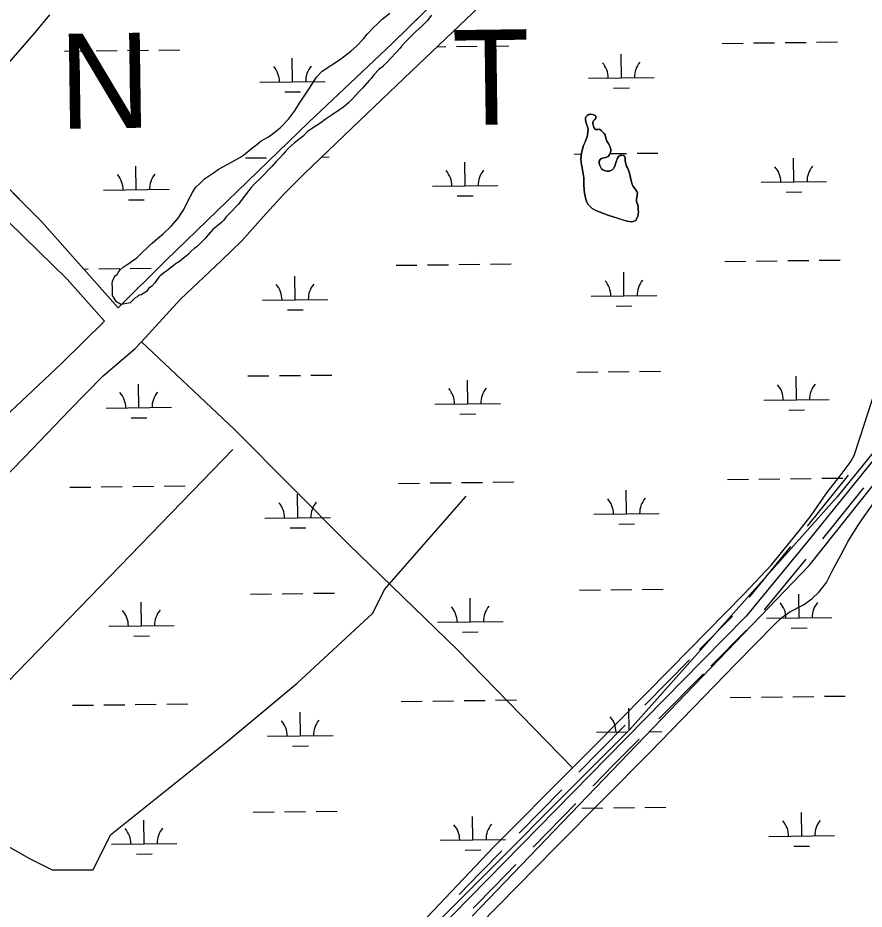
# Model space of a CAD drawing. Extents: x 3694830 to 3732949, y 415201 to 440970.
# Drawn here: x 3723273 to 3724564, y 421416 to 422776 of the extents above; entities that cross this region are included whole.
import ezdxf

# ---------------------------------------------------------------- set-up
doc = ezdxf.new("R2010")
doc.units = 0
for name, color, linetype in [('V-ROAD-CNTR', 7, 'Continuous'), ('V-SITE-VEGE', 7, 'Continuous'), ('V-TOPO-GNAM-IDEN', 7, 'Continuous'), ('V-TOPO-SHOR', 7, 'Continuous'), ('V-WETL-SWMP', 7, 'Continuous')]:
    doc.layers.add(name, color=color, linetype=linetype)

msp = doc.modelspace()

# ---------------------------------------------------------------- linework, layer by layer
at = {"layer": 'V-ROAD-CNTR'}
for points in [[(3724786.4, 422355), (3724602.6, 422131.6), (3724478.4, 421977.9), (3724384.4, 421863.4), (3724317.6, 421795.5)], [(3724540.2, 422078.3), (3724477.4, 422000.5)], [(3724563.5, 422059.4), (3724500.7, 421981.6)], [(3724452.2, 421969.6), (3724388.7, 421892.3)], [(3724475.3, 421950.5), (3724411.9, 421873.3)], [(3724363.2, 421863.3), (3724313.1, 421812.4)], [(3724384.6, 421842.2), (3724330.5, 421787.3)], [(3724317.6, 421795.5), (3724172.3, 421648), (3723806.9, 421275.5), (3723498.2, 420963.7)], [(3724297.7, 421796.8), (3724229.8, 421727.7)], [(3724319, 421775.6), (3724251.2, 421706.7)], [(3724199.5, 421697), (3724161.6, 421658.5)], [(3724220.9, 421675.9), (3724183, 421637.4)], [(3724161.6, 421658.5), (3724129, 421625.2)], [(3724183, 421637.4), (3724150.4, 421604.2)], [(3724102.9, 421598.6), (3724037.6, 421532.1)], [(3724124.3, 421577.6), (3724059, 421511.1)], [(3724011.5, 421505.5), (3723978.9, 421472.2)], [(3723978.9, 421472.2), (3723946.3, 421439)], [(3724032.9, 421484.5), (3724000.3, 421451.2)], [(3724000.3, 421451.2), (3723967.7, 421418)]]:
    msp.add_lwpolyline(points, dxfattribs=at)
at = {"layer": 'V-SITE-VEGE'}
for points in [[(3723469.1, 422358.5), (3723460.6, 422353.8), (3723458.1, 422353.2), (3723456.2, 422352), (3723454.4, 422350.1), (3723451.9, 422348.9), (3723450, 422347.7), (3723448.8, 422345.8), (3723443.8, 422341.5), (3723438.9, 422340.2), (3723429.6, 422339), (3723427.7, 422340.2), (3723423.4, 422342.7), (3723420.9, 422345.8), (3723419.7, 422348.3), (3723417.2, 422352.6), (3723417.2, 422366.2), (3723416.6, 422370), (3723417.2, 422374.3), (3723419.7, 422379.9), (3723421.6, 422383), (3723424, 422384.8), (3723425.9, 422387.9), (3723429, 422391.6), (3723433.3, 422396), (3723439.5, 422399.7), (3723442, 422401.5), (3723445.9, 422404.6), (3723454, 422410.1), (3723458.9, 422414.5), (3723472.5, 422428.1), (3723477.5, 422432.4), (3723485.5, 422439.8), (3723494.2, 422446.6), (3723507.2, 422459), (3723517.1, 422470.8), (3723522.7, 422479.4), (3723525.8, 422483.8), (3723533.2, 422498.6), (3723539.4, 422509.8), (3723543.8, 422517.2), (3723550.6, 422523.4), (3723557.4, 422530.8), (3723571, 422539.5), (3723579.7, 422545.7), (3723593.3, 422553.1), (3723603.2, 422558.7), (3723612.5, 422563.6), (3723616.8, 422566.7), (3723628.6, 422576.6), (3723637.3, 422582.8), (3723644.1, 422588.4), (3723655.2, 422594.6), (3723660.8, 422598.9), (3723673.2, 422608.2), (3723685.6, 422621.8), (3723694.9, 422633.6), (3723703.5, 422647.8), (3723717.8, 422668.8), (3723728.3, 422685.5), (3723737, 422694.8), (3723764.9, 422713.4), (3723781, 422725.2), (3723789.6, 422733.2), (3723800.2, 422744.3), (3723805.7, 422751.1), (3723816.3, 422762.3), (3723821.2, 422766.6), (3723828.6, 422774), (3723840.4, 422783.3)], [(3723904.2, 422780.2), (3723897.4, 422771.5), (3723889.9, 422764.1), (3723879.4, 422754.8), (3723862.1, 422737.5), (3723858.3, 422733.2), (3723855.9, 422730.1), (3723835.4, 422707.8), (3723830.5, 422703.5), (3723829.2, 422701.6), (3723824.3, 422697.9), (3723816.2, 422689.2), (3723811.9, 422683.7), (3723809.4, 422681.2), (3723798.9, 422668.8), (3723793.3, 422663.2), (3723783.4, 422652.7), (3723777.2, 422646.5), (3723769.8, 422639.7), (3723763.6, 422636), (3723752.4, 422628), (3723741.9, 422621.2), (3723735.1, 422616.2), (3723720.9, 422606.9), (3723714.7, 422602.6), (3723707.9, 422595.8), (3723694.9, 422585.3), (3723685.6, 422577.2), (3723680.6, 422571.6), (3723676.9, 422567.9), (3723672.6, 422562.4), (3723667, 422556.8), (3723660.2, 422549.4), (3723641, 422529.6), (3723634.8, 422524), (3723628.6, 422517.2), (3723619.9, 422506), (3723615, 422499.8), (3723609.4, 422491.8), (3723596.4, 422478.2), (3723590.8, 422472.6), (3723586.5, 422467), (3723584, 422464.6), (3723570.4, 422453.4), (3723559.8, 422441.7), (3723558.6, 422439.8), (3723545.6, 422426.8), (3723541.9, 422424.3), (3723536.9, 422420), (3723532.6, 422415.1), (3723530.1, 422413.2), (3723517.7, 422403.3), (3723514.6, 422402.1), (3723509.1, 422397.1), (3723507.2, 422395.9), (3723499.8, 422390.3), (3723495.4, 422387.2), (3723489.2, 422382.3), (3723488, 422380.4), (3723483.7, 422374.8), (3723481.8, 422371.7), (3723476.9, 422366.8), (3723471.9, 422363.1), (3723470.7, 422360.6), (3723469.1, 422358.5)]]:
    msp.add_lwpolyline(points, dxfattribs=at)
at = {"layer": 'V-TOPO-SHOR'}
msp.add_line((3723053.4, 421553.2), (3723600.9, 422117.5), dxfattribs=at)
for points in [[(3723843.6, 422736.3), (3723921.9, 422813.8)], [(3723873.4, 422694.7), (3723977.1, 422793.5)], [(3723321.1, 422780.8), (3723299, 422754.3), (3723238, 422684.7)], [(3723425.5, 422333.8), (3723499.1, 422406.4), (3723716.6, 422617.2), (3723843.6, 422736.3)], [(3723191.8, 422013.3), (3723283.2, 422106.5), (3723351.6, 422177.8), (3723402.8, 422229.8), (3723451, 422271.1), (3723461.1, 422282.1), (3723520.8, 422346.9), (3723583.4, 422405.8), (3723614.3, 422436.2), (3723647, 422472.6), (3723678.2, 422506.7), (3723709.6, 422538.4), (3723782.6, 422607.9), (3723873.4, 422694.7)], [(3723233.6, 422648), (3723224.2, 422631.8), (3723206.7, 422605.2), (3723201.9, 422591.2), (3723201.1, 422581.5), (3723205.4, 422571.5), (3723220.7, 422553.5), (3723308.7, 422465.5), (3723425.5, 422333.8)], [(3724218.8, 422473.6), (3724215.9, 422467.1), (3724213.3, 422465.8), (3724209.4, 422464.9), (3724202.4, 422465.8), (3724194.8, 422468.2), (3724187.3, 422470.7), (3724179.5, 422473.2), (3724173, 422475.3), (3724168.1, 422477.3), (3724161.5, 422479.7), (3724154.7, 422482.3), (3724149.2, 422485.4), (3724143.2, 422491.2), (3724141.2, 422495), (3724139.7, 422499.7), (3724137.5, 422508.9), (3724136.3, 422520.3), (3724136.5, 422525.9), (3724136.5, 422532), (3724133.8, 422547.6), (3724133, 422551.7), (3724132.5, 422556.7), (3724132.1, 422560.7), (3724132.4, 422565.3), (3724133, 422570.3), (3724136, 422581.3), (3724137.8, 422585.5), (3724139.7, 422589.6), (3724141.4, 422594.9), (3724142.8, 422601.3), (3724143, 422606.6), (3724141.6, 422611.2), (3724140.1, 422615.6), (3724139.1, 422620.5), (3724139, 422623.9), (3724139.9, 422625.6), (3724140.6, 422626.4), (3724141.5, 422627.4), (3724144.3, 422628.7), (3724146.8, 422629.1), (3724150.1, 422628.7), (3724151.6, 422628.4), (3724153.6, 422627.4), (3724154.8, 422626.2), (3724154.9, 422623.3), (3724152.6, 422620.6), (3724150.6, 422618.4), (3724150, 422615.3), (3724150.6, 422612.9), (3724152, 422608.7), (3724154.5, 422606.1), (3724155.8, 422605.7), (3724157.8, 422605.9), (3724160.2, 422606.2), (3724160.8, 422606.1), (3724163.1, 422604.3), (3724165.6, 422601.8), (3724167.6, 422599.6), (3724169, 422597.5), (3724169.8, 422594.5), (3724170.5, 422591.1), (3724171.7, 422587.8), (3724173.1, 422585.9), (3724174.9, 422583.4), (3724175.9, 422581.2), (3724177.1, 422577.6), (3724177.5, 422575.4), (3724177.5, 422572.7), (3724176.8, 422569.9), (3724175.5, 422567.6), (3724173.8, 422564.8), (3724170.1, 422563.1), (3724166.9, 422562.5), (3724163.6, 422561.6), (3724161.6, 422560), (3724160, 422557.5), (3724160, 422554.5), (3724160.7, 422551.1), (3724163.7, 422545.9), (3724166.3, 422544), (3724168.9, 422542.9), (3724172.2, 422542.1), (3724175.8, 422542.3), (3724179.5, 422544.1), (3724181.7, 422546.2), (3724183.9, 422550.1), (3724184.9, 422553.7), (3724186.4, 422558), (3724188.1, 422562), (3724189.5, 422564.5), (3724191.8, 422566.2), (3724194.3, 422566.9), (3724197, 422566.4), (3724199.2, 422564.5), (3724199.7, 422560.9), (3724199.7, 422557.5), (3724201.7, 422550), (3724203.4, 422547.2), (3724204.9, 422543.7), (3724206.2, 422539)], [(3723170.6, 422547.3), (3723190.8, 422530.4), (3723347.7, 422377.5), (3723405, 422313.6)], [(3724206.2, 422539), (3724207.5, 422532.8), (3724208.7, 422527.5), (3724210.2, 422522.3), (3724211.6, 422518.9), (3724213.7, 422516.1), (3724216, 422513.7), (3724217.5, 422511.2), (3724218.2, 422508.5), (3724218.1, 422505.1), (3724216.9, 422500.3), (3724216.9, 422496.2), (3724217.5, 422494.2), (3724218.2, 422492.3), (3724219.2, 422488.8), (3724219.6, 422483.7), (3724219.7, 422479.8), (3724219.4, 422476.9), (3724218.8, 422473.6)], [(3723198.6, 422117.2), (3723339.2, 422248.7), (3723405, 422313.6)], [(3723461.1, 422282.1), (3723603.4, 422148.3), (3723777.2, 421973.2), (3723943.4, 421812.5), (3724119.4, 421632.2)], [(3723870.1, 421375.4), (3723998.4, 421511), (3724119.4, 421632.2), (3724153, 421665.8), (3724268.1, 421782.5), (3724380.9, 421897.1), (3724422.7, 421941.9), (3724447.4, 421971.7), (3724465.4, 421993.7), (3724483.4, 422016.8), (3724507.5, 422051.4), (3724527.7, 422077.7), (3724543, 422097.8), (3724548.9, 422108.3), (3724558.5, 422136.7), (3724593.4, 422244.6)], [(3723129.1, 421601.2), (3723227, 421529.9), (3723289.3, 421494.3), (3723325, 421476.5), (3723387.3, 421476.5), (3723414, 421529.9), (3723592, 421672.4), (3723698.9, 421761.4), (3723814.6, 421868.2), (3723832.4, 421903.9), (3723957, 422046.3)], [(3723976.2, 421391.7), (3724093.6, 421511), (3724237.4, 421655.3), (3724368.7, 421790.9), (3724427.4, 421850.6), (3724438.6, 421861.6), (3724450.9, 421870.1), (3724471.7, 421880.8), (3724484.3, 421889.6), (3724495.7, 421900.3), (3724506.7, 421914.9), (3724516.8, 421933.9), (3724528.6, 421956.6), (3724539.8, 421977.9), (3724557.1, 422005.1), (3724580.3, 422037.7)]]:
    msp.add_lwpolyline(points, dxfattribs=at)
at = {"layer": 'V-WETL-SWMP'}
for p, q in [((3723921.9, 422813.8), (3723843.6, 422736.3)), ((3723873.5, 422694.7), (3723977.1, 422793.5)), ((3723843.6, 422736.3), (3723716.6, 422617.2)), ((3724347.7, 422737.3), (3724379.7, 422737.7)), ((3724395.7, 422737.9), (3724427.7, 422738.3)), ((3724443.7, 422738.4), (3724475.7, 422738.8)), ((3724491.7, 422739), (3724523.7, 422739.4)), ((3723344, 422725.3), (3723376, 422725.7)), ((3723392, 422725.9), (3723424, 422726.3)), ((3723440, 422726.5), (3723472, 422726.9)), ((3723488, 422727), (3723520, 422727.4)), ((3723912.6, 422732.1), (3723925.9, 422732.3)), ((3723941.9, 422732.5), (3723973.9, 422732.8)), ((3723989.9, 422733), (3724021.9, 422733.4)), ((3723691.9, 422678.7), (3723691.5, 422714.7)), ((3724193.8, 422684.7), (3724193.3, 422720.7)), ((3723782.6, 422607.9), (3723873.5, 422694.7)), ((3724143.8, 422684.1), (3724243.8, 422685.3)), ((3723641.9, 422678.1), (3723741.9, 422679.3)), ((3724182, 422669.1), (3724206, 422669.4)), ((3723680.1, 422663.2), (3723704.1, 422663.4)), ((3724141.5, 422627.4), (3724139.9, 422625.6)), ((3724144.3, 422628.7), (3724141.5, 422627.4)), ((3724146.8, 422629.1), (3724144.3, 422628.7)), ((3724151.6, 422628.4), (3724146.8, 422629.1)), ((3724153.6, 422627.4), (3724151.6, 422628.4)), ((3724154.8, 422626.2), (3724153.6, 422627.4)), ((3723716.6, 422617.2), (3723499.1, 422406.4)), ((3724139.9, 422625.6), (3724139, 422623.9)), ((3724139, 422623.9), (3724139.1, 422620.5)), ((3724139.1, 422620.5), (3724140.1, 422615.6)), ((3724140.1, 422615.6), (3724141.7, 422611.2)), ((3724150, 422615.3), (3724150.6, 422618.4)), ((3724152, 422608.7), (3724150, 422615.3)), ((3724150.6, 422618.4), (3724154.9, 422623.3)), ((3724154.9, 422623.3), (3724154.8, 422626.2)), ((3723709.6, 422538.4), (3723782.6, 422607.9)), ((3724142.8, 422601.3), (3724141.4, 422594.9)), ((3724141.7, 422611.2), (3724143, 422606.6)), ((3724143, 422606.6), (3724142.8, 422601.3)), ((3724154.5, 422606.1), (3724152, 422608.7)), ((3724155.8, 422605.7), (3724154.5, 422606.1)), ((3724160.2, 422606.2), (3724155.8, 422605.7)), ((3724160.8, 422606.1), (3724160.2, 422606.2)), ((3724163.1, 422604.3), (3724160.8, 422606.1)), ((3724165.6, 422601.8), (3724163.1, 422604.3)), ((3724167.6, 422599.6), (3724165.6, 422601.8)), ((3724139.7, 422589.6), (3724136, 422581.3)), ((3724141.4, 422594.9), (3724139.7, 422589.6)), ((3724169, 422597.5), (3724167.6, 422599.6)), ((3724169.8, 422594.5), (3724169, 422597.5)), ((3724170.5, 422591.1), (3724169.8, 422594.5)), ((3724171.7, 422587.8), (3724170.5, 422591.1)), ((3724173.1, 422585.9), (3724171.7, 422587.8)), ((3724136, 422581.3), (3724133, 422570.3)), ((3724174.9, 422583.4), (3724173.1, 422585.9)), ((3724175.9, 422581.2), (3724174.9, 422583.4)), ((3724177.1, 422577.6), (3724175.9, 422581.2)), ((3724176.8, 422569.9), (3724177.5, 422572.7)), ((3724177.5, 422575.4), (3724177.1, 422577.6)), ((3724177.5, 422572.7), (3724177.5, 422575.4)), ((3723619.9, 422562.4), (3723651.9, 422562.8)), ((3723736.3, 422563.8), (3723747.9, 422564)), ((3724121.7, 422568.4), (3724132.8, 422568.5)), ((3724132.4, 422565.3), (3724132.1, 422560.7)), ((3724132.1, 422560.7), (3724133, 422551.7)), ((3724133, 422570.3), (3724132.4, 422565.3)), ((3724160, 422557.5), (3724161.6, 422560)), ((3724161.6, 422560), (3724163.6, 422561.6)), ((3724163.6, 422561.6), (3724166.9, 422562.5)), ((3724166.9, 422562.5), (3724170.1, 422563.1)), ((3724170.1, 422563.1), (3724173.8, 422564.8)), ((3724173.8, 422564.8), (3724175.5, 422567.6)), ((3724175.5, 422567.6), (3724176.8, 422569.9)), ((3724176.4, 422569.1), (3724201.7, 422569.4)), ((3724188.1, 422562), (3724186.4, 422558)), ((3724189.5, 422564.5), (3724188.1, 422562)), ((3724191.8, 422566.2), (3724189.5, 422564.5)), ((3724194.3, 422566.9), (3724191.8, 422566.2)), ((3724197, 422566.4), (3724194.3, 422566.9)), ((3724199.2, 422564.5), (3724197, 422566.4)), ((3724199.7, 422560.9), (3724199.2, 422564.5)), ((3724199.7, 422557.5), (3724199.7, 422560.9)), ((3724217.7, 422569.6), (3724249.7, 422569.9)), ((3724457.1, 422526), (3724456.7, 422562)), ((3723308.7, 422465.5), (3723220.7, 422553.5)), ((3723453.4, 422514), (3723452.9, 422550)), ((3723955.2, 422520), (3723954.8, 422556)), ((3724133, 422551.7), (3724133.8, 422547.6)), ((3724133.8, 422547.6), (3724136.5, 422532)), ((3724160, 422554.5), (3724160, 422557.5)), ((3724160.7, 422551.1), (3724160, 422554.5)), ((3724163.7, 422545.9), (3724160.7, 422551.1)), ((3724166.3, 422544), (3724163.7, 422545.9)), ((3724181.7, 422546.2), (3724179.5, 422544.1)), ((3724183.9, 422550.1), (3724181.7, 422546.2)), ((3724184.9, 422553.7), (3724183.9, 422550.1)), ((3724186.4, 422558), (3724184.9, 422553.7)), ((3724201.7, 422550), (3724199.7, 422557.5)), ((3724203.4, 422547.2), (3724201.7, 422550)), ((3724204.9, 422543.7), (3724203.4, 422547.2)), ((3723678.2, 422506.7), (3723709.6, 422538.4)), ((3724136.5, 422532), (3724136.5, 422525.9)), ((3724168.9, 422542.9), (3724166.3, 422544)), ((3724172.2, 422542.1), (3724168.9, 422542.9)), ((3724175.8, 422542.3), (3724172.2, 422542.1)), ((3724179.5, 422544.1), (3724175.8, 422542.3)), ((3724206.2, 422539), (3724204.9, 422543.7)), ((3724208.7, 422527.5), (3724206.2, 422539)), ((3723905.3, 422519.4), (3724005.2, 422520.6)), ((3724136.5, 422525.9), (3724136.3, 422520.3)), ((3724136.3, 422520.3), (3724137.5, 422508.9)), ((3724210.2, 422522.3), (3724208.7, 422527.5)), ((3724211.6, 422518.9), (3724210.2, 422522.3)), ((3724213.8, 422516.1), (3724211.6, 422518.9)), ((3724407.1, 422525.4), (3724507.1, 422526.6)), ((3723403.4, 422513.4), (3723503.4, 422514.6)), ((3723647, 422472.6), (3723678.2, 422506.7)), ((3723943.4, 422504.4), (3723967.4, 422504.7)), ((3724137.5, 422508.9), (3724139.7, 422499.7)), ((3724216, 422513.7), (3724213.8, 422516.1)), ((3724217.5, 422511.2), (3724216, 422513.7)), ((3724216.9, 422500.3), (3724218.1, 422505.1)), ((3724218.2, 422508.5), (3724217.5, 422511.2)), ((3724218.1, 422505.1), (3724218.2, 422508.5)), ((3724445.3, 422510.4), (3724469.3, 422510.7)), ((3723441.6, 422498.4), (3723465.6, 422498.7)), ((3724139.7, 422499.7), (3724141.2, 422495)), ((3724141.2, 422495), (3724143.2, 422491.2)), ((3724143.2, 422491.2), (3724149.2, 422485.4)), ((3724216.9, 422496.2), (3724216.9, 422500.3)), ((3724217.5, 422494.2), (3724216.9, 422496.2)), ((3724218.2, 422492.3), (3724217.5, 422494.2)), ((3724219.2, 422488.8), (3724218.2, 422492.3)), ((3724149.2, 422485.4), (3724154.7, 422482.3)), ((3724154.7, 422482.3), (3724161.5, 422479.7)), ((3724161.5, 422479.7), (3724168.1, 422477.3)), ((3724168.1, 422477.3), (3724173, 422475.3)), ((3724219.6, 422483.7), (3724219.2, 422488.8)), ((3724219.4, 422476.9), (3724219.7, 422479.8)), ((3724219.7, 422479.8), (3724219.6, 422483.7)), ((3723425.5, 422333.8), (3723308.7, 422465.5)), ((3723614.3, 422436.2), (3723647, 422472.6)), ((3724173, 422475.3), (3724202.4, 422465.8)), ((3724202.4, 422465.8), (3724209.4, 422464.9)), ((3724209.4, 422464.9), (3724213.3, 422465.8)), ((3724213.3, 422465.8), (3724215.9, 422467.1)), ((3724215.9, 422467.1), (3724218.8, 422473.6)), ((3724218.8, 422473.6), (3724219.4, 422476.9)), ((3723583.4, 422405.8), (3723614.3, 422436.2)), ((3723499.1, 422406.4), (3723425.5, 422333.8)), ((3723520.8, 422346.9), (3723583.4, 422405.8)), ((3723849.8, 422398.7), (3723881.8, 422399)), ((3723897.8, 422399.2), (3723929.8, 422399.6)), ((3723945.8, 422399.8), (3723977.8, 422400.2)), ((3723993.8, 422400.4), (3724025.8, 422400.8)), ((3724351.7, 422404.6), (3724383.7, 422405)), ((3724399.7, 422405.2), (3724431.7, 422405.6)), ((3724447.7, 422405.8), (3724479.7, 422406.2)), ((3724495.7, 422406.4), (3724527.7, 422406.7)), ((3723373.1, 422393), (3723380, 422393.1)), ((3723396, 422393.2), (3723428, 422393.6)), ((3723444, 422393.8), (3723476, 422394.2)), ((3724197.7, 422352.1), (3724197.3, 422388.1)), ((3723695.9, 422346.1), (3723695.4, 422382.1)), ((3723461.1, 422282.1), (3723520.8, 422346.9)), ((3723645.9, 422345.5), (3723745.9, 422346.7)), ((3724147.7, 422351.5), (3724247.7, 422352.7)), ((3723684.1, 422330.5), (3723708.1, 422330.8)), ((3724185.9, 422336.5), (3724209.9, 422336.8)), ((3723451, 422271.1), (3723461.1, 422282.1)), ((3723402.8, 422229.8), (3723451, 422271.1)), ((3724125.7, 422235.8), (3724157.7, 422236.1)), ((3724173.7, 422236.3), (3724205.7, 422236.7)), ((3724221.7, 422236.9), (3724253.7, 422237.3)), ((3723351.6, 422177.8), (3723402.8, 422229.8)), ((3723623.8, 422229.8), (3723655.8, 422230.2)), ((3723671.8, 422230.4), (3723703.8, 422230.7)), ((3723719.8, 422230.9), (3723751.8, 422231.3)), ((3723959.2, 422187.3), (3723958.8, 422223.3)), ((3724461.1, 422193.3), (3724460.7, 422229.3)), ((3723457.3, 422181.4), (3723456.9, 422217.4)), ((3724660.1, 422214), (3724523.2, 422045.6)), ((3724411.1, 422192.7), (3724511.1, 422193.9)), ((3723407.3, 422180.8), (3723507.3, 422182)), ((3723909.2, 422186.7), (3724009.2, 422187.9)), ((3723283.2, 422106.5), (3723351.6, 422177.8)), ((3723445.5, 422165.8), (3723469.5, 422166.1)), ((3723947.4, 422171.8), (3723971.4, 422172.1)), ((3724449.3, 422177.8), (3724473.3, 422178)), ((3723191.8, 422013.3), (3723283.2, 422106.5)), ((3724480.8, 421941.4), (3724609.2, 422102.5)), ((3724355.7, 422072), (3724387.7, 422072.4)), ((3724403.7, 422072.6), (3724435.7, 422072.9)), ((3724451.7, 422073.1), (3724483.7, 422073.5)), ((3724499.7, 422073.7), (3724531.7, 422074.1)), ((3723351.9, 422060), (3723383.9, 422060.4)), ((3723399.9, 422060.6), (3723431.9, 422061)), ((3723447.9, 422061.2), (3723479.9, 422061.5)), ((3723495.9, 422061.7), (3723527.9, 422062.1)), ((3723853.8, 422066), (3723885.8, 422066.4)), ((3723901.8, 422066.6), (3723933.8, 422067)), ((3723949.8, 422067.2), (3723981.8, 422067.5)), ((3723997.8, 422067.7), (3724029.8, 422068.1)), ((3723699.8, 422013.4), (3723699.4, 422049.4)), ((3724201.7, 422019.4), (3724201.3, 422055.4)), ((3724523.2, 422045.6), (3724206.9, 421690.6)), ((3724151.7, 422018.8), (3724251.7, 422020)), ((3723649.8, 422012.8), (3723749.8, 422014)), ((3724189.9, 422003.8), (3724213.9, 422004.1)), ((3723688, 421997.9), (3723712, 421998.1)), ((3723965.8, 421405.9), (3724480.8, 421941.4)), ((3723627.8, 421897.1), (3723659.8, 421897.5)), ((3723675.8, 421897.7), (3723707.8, 421898.1)), ((3723723.8, 421898.3), (3723755.8, 421898.7)), ((3724129.7, 421903.1), (3724161.7, 421903.5)), ((3724177.7, 421903.7), (3724209.7, 421904.1)), ((3724225.7, 421904.3), (3724257.7, 421904.6)), ((3724465.1, 421860.7), (3724464.6, 421896.7)), ((3723461.3, 421848.7), (3723460.9, 421884.7)), ((3723963.2, 421854.7), (3723962.8, 421890.7)), ((3723913.2, 421854.1), (3724013.2, 421855.3)), ((3724415.1, 421860.1), (3724515.1, 421861.3)), ((3723411.3, 421848.1), (3723511.3, 421849.3)), ((3723951.4, 421839.1), (3723975.4, 421839.4)), ((3724453.2, 421845.1), (3724477.2, 421845.4)), ((3723449.5, 421833.1), (3723473.5, 421833.4)), ((3723499.9, 421729.1), (3723531.9, 421729.5)), ((3723857.8, 421733.4), (3723889.8, 421733.7)), ((3723905.8, 421733.9), (3723937.8, 421734.3)), ((3723953.8, 421734.5), (3723985.8, 421734.9)), ((3724001.8, 421735.1), (3724033.8, 421735.5)), ((3724359.7, 421739.3), (3724391.6, 421739.7)), ((3724407.6, 421739.9), (3724439.6, 421740.3)), ((3724455.6, 421740.5), (3724487.6, 421740.9)), ((3724503.6, 421741.1), (3724535.6, 421741.4)), ((3723355.9, 421727.4), (3723387.9, 421727.8)), ((3723403.9, 421727.9), (3723435.9, 421728.3)), ((3723451.9, 421728.5), (3723483.9, 421728.9)), ((3723703.8, 421680.8), (3723703.4, 421716.8)), ((3724205.6, 421689.3), (3724205.2, 421722.8)), ((3724206.9, 421690.6), (3723821.6, 421305.4)), ((3723653.8, 421680.2), (3723753.8, 421681.4)), ((3724155.7, 421686.2), (3724203, 421686.7)), ((3724236.2, 421687.1), (3724255.7, 421687.4)), ((3723692, 421665.2), (3723716, 421665.5)), ((3724133.6, 421570.5), (3724165.6, 421570.8)), ((3724181.6, 421571), (3724213.6, 421571.4)), ((3724229.6, 421571.6), (3724261.6, 421572)), ((3723631.8, 421564.5), (3723663.8, 421564.9)), ((3723679.8, 421565), (3723711.8, 421565.4)), ((3723727.8, 421565.6), (3723759.8, 421566)), ((3723967.2, 421522), (3723966.7, 421558)), ((3724469, 421528), (3724468.6, 421564)), ((3723465.3, 421516.1), (3723464.8, 421552.1)), ((3724419, 421527.4), (3724519, 421528.6)), ((3723415.3, 421515.5), (3723515.3, 421516.7)), ((3723917.2, 421521.4), (3724017.1, 421522.6)), ((3724457.2, 421512.5), (3724481.2, 421512.7)), ((3723453.5, 421500.5), (3723477.5, 421500.8)), ((3723955.3, 421506.5), (3723979.3, 421506.8))]:
    msp.add_line(p, q, dxfattribs=at)
msp.add_lwpolyline([(3723190.8, 422530.4), (3723347.7, 422377.5), (3723405, 422313.6), (3723339.2, 422248.7), (3723198.6, 422117.2)], dxfattribs=at)
for centre, start, end in [((3724249, 422685.8), 139.9115, 181.4552), ((3723636.7, 422678.5), 359.9115, 41.4552), ((3723747.1, 422679.9), 139.9115, 181.4552), ((3724138.5, 422684.5), 359.9115, 41.4552), ((3724401.9, 422525.8), 359.9115, 41.4552), ((3724512.4, 422527.1), 139.9115, 181.4552), ((3723398.1, 422513.8), 359.9115, 41.4552), ((3723508.6, 422515.1), 139.9115, 181.4552), ((3723900, 422519.8), 359.9115, 41.4552), ((3724010.5, 422521.1), 139.9115, 181.4552), ((3723640.6, 422345.9), 359.9115, 41.4552), ((3723751.1, 422347.2), 139.9115, 181.4552), ((3724142.5, 422351.9), 359.9115, 41.4552), ((3724253, 422353.2), 139.9115, 181.4552), ((3723904, 422187.2), 359.9115, 41.4552), ((3724014.4, 422188.5), 139.9115, 181.4552), ((3724405.8, 422193.1), 359.9115, 41.4552), ((3724516.3, 422194.5), 139.9115, 181.4552), ((3723402.1, 422181.2), 359.9115, 41.4552), ((3723512.6, 422182.5), 139.9115, 181.4552), ((3724146.5, 422019.2), 359.9115, 41.4552), ((3724256.9, 422020.5), 139.9115, 181.4552), ((3723644.6, 422013.2), 359.9115, 41.4552), ((3723755.1, 422014.6), 139.9115, 181.4552), ((3724409.8, 421860.5), 359.9115, 41.4552), ((3724520.3, 421861.8), 139.9115, 181.4552), ((3723406.1, 421848.5), 359.9115, 41.4552), ((3723516.5, 421849.8), 139.9115, 181.4552), ((3723907.9, 421854.5), 359.9115, 41.4552), ((3724018.4, 421855.8), 139.9115, 181.4552), ((3723648.6, 421680.6), 359.9115, 41.4552), ((3723759, 421681.9), 139.9115, 181.4552), ((3724150.4, 421686.6), 359.9115, 41.4552), ((3723410, 421515.9), 359.9115, 41.4552), ((3723520.5, 421517.2), 139.9115, 181.4552), ((3723911.9, 421521.9), 359.9115, 41.4552), ((3724022.4, 421523.2), 139.9115, 181.4552), ((3724413.8, 421527.8), 359.9115, 41.4552), ((3724524.3, 421529.2), 139.9115, 181.4552)]:
    msp.add_arc(centre, 35.2, start, end, dxfattribs=at)

# ---------------------------------------------------------------- texts
at = {"layer": 'V-TOPO-GNAM-IDEN'}
for s, p in [('N', (3723336.4, 422606.8)), ('T', (3723936.6, 422612.4))]:
    msp.add_text(s, height=145, rotation=0.7812, dxfattribs=at).set_placement(p)

doc.saveas('drawing.dxf')
